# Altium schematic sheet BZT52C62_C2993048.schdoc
size 127 x 101 mm
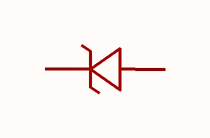
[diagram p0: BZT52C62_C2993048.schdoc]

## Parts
D?  bzt52c62_c2993048  [SOD-123_L2.7-W1.6-LS3.7-RD]  (value not drawn)

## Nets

Not connected (* = marked no-connect by the designer): D? 1(C) 2(A)

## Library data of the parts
D? = bzt52c62_c2993048: 二极管配置:1个独立式;稳压值(标称值):62V;稳压值(范围):58V~66V;耗散功率(Pd):500mW;; Manufacturer: MDD(辰达半导体); AddInBom: yes; ModelId: ad7e39f9e5534b3c96ffdc5532ebb493; ModelName: SOD-123_L2.7-W1.6-H1.4-LS3.7; ModelTransform: 146.026,62.992,0,180,0,0,0.0005,0,0; Diode Configuration: 1个独立式; Zener Voltage(Nom): 62V; Reverse Leakage Current (Ir): 200nA@47V; Pd - Power Dissipation: 500mW; Impedance(Zzt): 200Ω; Tolerance: ±5%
